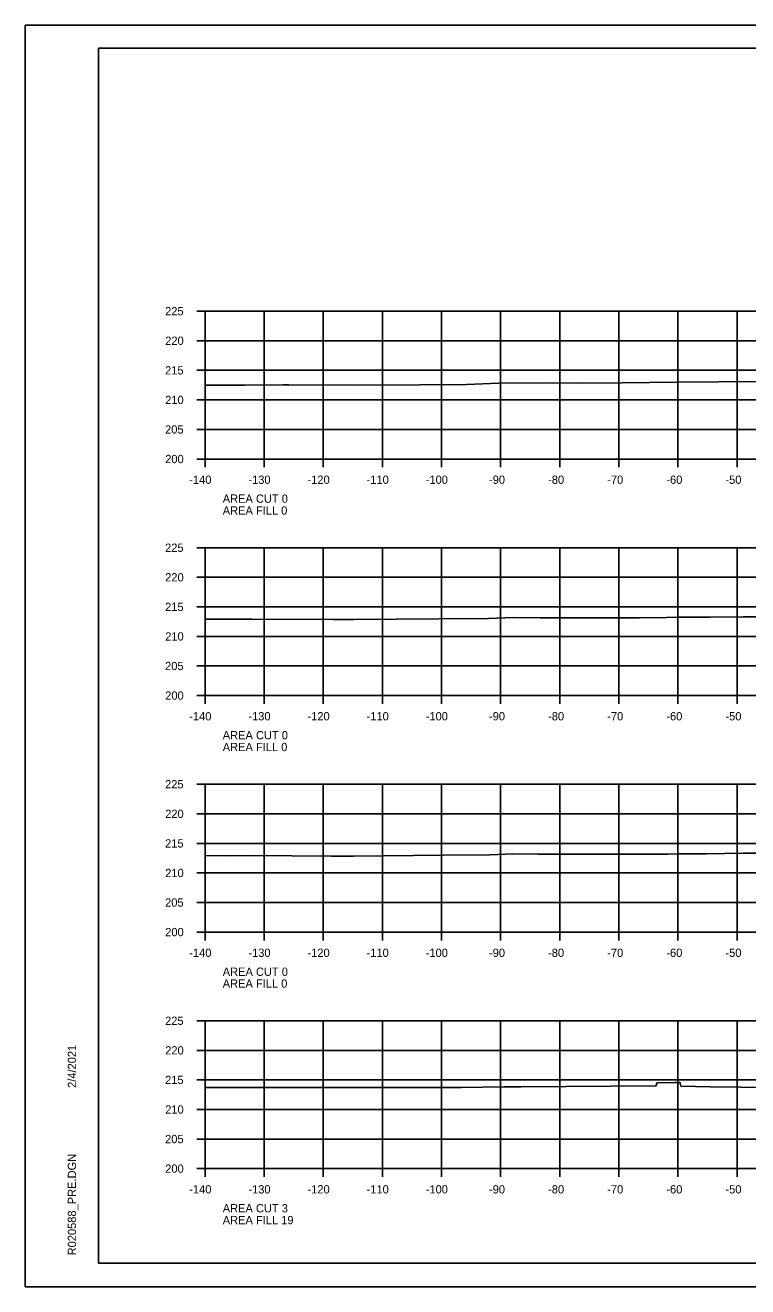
# Model space of a CAD drawing. Extents: x 1368968 to 1369915, y 377395 to 380381.
# Drawn here: x 1369581.4 to 1369703.6, y 379954.8 to 380168.1 of the extents above; entities that cross this region are included whole.
import ezdxf

# ---------------------------------------------------------------- set-up
doc = ezdxf.new("R2010")
doc.units = 0
for name, color, linetype in [('S_BREAKLINE_ANNOT', 7, 'Continuous'), ('S_BRIDGE', 7, 'Continuous'), ('S_BRIDGE_ANNOT', 7, 'Continuous'), ('S_CTL_TABLE', 7, 'Continuous'), ('S_DITCHLINE_ANNOT', 7, 'Continuous'), ('S_DROP_INLET', 7, 'Continuous')]:
    doc.layers.add(name, color=color, linetype=linetype)

msp = doc.modelspace()

# ---------------------------------------------------------------- linework, layer by layer
at = {"layer": 'S_BREAKLINE_ANNOT'}
for p, q in [((1369610.38, 380119.73), (1369611.78, 380119.73)), ((1369611.78, 380094.73), (1369611.78, 380119.73)), ((1369610.38, 380114.73), (1369611.78, 380114.73)), ((1369610.38, 380109.73), (1369611.78, 380109.73)), ((1369610.38, 380104.73), (1369611.78, 380104.73)), ((1369610.38, 380099.73), (1369611.78, 380099.73)), ((1369610.38, 380094.73), (1369611.78, 380094.73)), ((1369611.78, 380094.73), (1369891.78, 380094.73)), ((1369611.78, 380093.33), (1369611.78, 380094.73)), ((1369621.78, 380093.33), (1369621.78, 380094.73)), ((1369631.78, 380093.33), (1369631.78, 380094.73)), ((1369641.78, 380093.33), (1369641.78, 380094.73)), ((1369651.78, 380093.33), (1369651.78, 380094.73)), ((1369661.78, 380093.33), (1369661.78, 380094.73)), ((1369671.78, 380093.33), (1369671.78, 380094.73)), ((1369681.78, 380093.33), (1369681.78, 380094.73)), ((1369691.78, 380093.33), (1369691.78, 380094.73)), ((1369701.78, 380093.33), (1369701.78, 380094.73)), ((1369610.38, 380079.73), (1369611.78, 380079.73)), ((1369611.78, 380054.73), (1369611.78, 380079.73)), ((1369610.38, 380074.73), (1369611.78, 380074.73)), ((1369610.38, 380069.73), (1369611.78, 380069.73)), ((1369610.38, 380064.73), (1369611.78, 380064.73)), ((1369610.38, 380059.73), (1369611.78, 380059.73)), ((1369610.38, 380054.73), (1369611.78, 380054.73)), ((1369611.78, 380054.73), (1369891.78, 380054.73)), ((1369611.78, 380053.33), (1369611.78, 380054.73)), ((1369621.78, 380053.33), (1369621.78, 380054.73)), ((1369631.78, 380053.33), (1369631.78, 380054.73)), ((1369641.78, 380053.33), (1369641.78, 380054.73)), ((1369651.78, 380053.33), (1369651.78, 380054.73)), ((1369661.78, 380053.33), (1369661.78, 380054.73)), ((1369671.78, 380053.33), (1369671.78, 380054.73)), ((1369681.78, 380053.33), (1369681.78, 380054.73)), ((1369691.78, 380053.33), (1369691.78, 380054.73)), ((1369701.78, 380053.33), (1369701.78, 380054.73)), ((1369610.38, 380039.73), (1369611.78, 380039.73)), ((1369611.78, 380014.73), (1369611.78, 380039.73)), ((1369610.38, 380034.73), (1369611.78, 380034.73)), ((1369610.38, 380029.73), (1369611.78, 380029.73)), ((1369610.38, 380024.73), (1369611.78, 380024.73)), ((1369610.38, 380019.73), (1369611.78, 380019.73)), ((1369610.38, 380014.73), (1369611.78, 380014.73)), ((1369611.78, 380014.73), (1369891.78, 380014.73)), ((1369611.78, 380013.33), (1369611.78, 380014.73)), ((1369621.78, 380013.33), (1369621.78, 380014.73)), ((1369631.78, 380013.33), (1369631.78, 380014.73)), ((1369641.78, 380013.33), (1369641.78, 380014.73)), ((1369651.78, 380013.33), (1369651.78, 380014.73)), ((1369661.78, 380013.33), (1369661.78, 380014.73)), ((1369671.78, 380013.33), (1369671.78, 380014.73)), ((1369681.78, 380013.33), (1369681.78, 380014.73)), ((1369691.78, 380013.33), (1369691.78, 380014.73)), ((1369701.78, 380013.33), (1369701.78, 380014.73)), ((1369610.38, 379999.73), (1369611.78, 379999.73)), ((1369611.78, 379974.73), (1369611.78, 379999.73)), ((1369610.38, 379994.73), (1369611.78, 379994.73)), ((1369610.38, 379989.73), (1369611.78, 379989.73)), ((1369610.38, 379984.73), (1369611.78, 379984.73)), ((1369610.38, 379979.73), (1369611.78, 379979.73)), ((1369610.38, 379974.73), (1369611.78, 379974.73)), ((1369611.78, 379974.73), (1369891.78, 379974.73)), ((1369611.78, 379973.33), (1369611.78, 379974.73)), ((1369621.78, 379973.33), (1369621.78, 379974.73)), ((1369631.78, 379973.33), (1369631.78, 379974.73)), ((1369641.78, 379973.33), (1369641.78, 379974.73)), ((1369651.78, 379973.33), (1369651.78, 379974.73)), ((1369661.78, 379973.33), (1369661.78, 379974.73)), ((1369671.78, 379973.33), (1369671.78, 379974.73)), ((1369681.78, 379973.33), (1369681.78, 379974.73)), ((1369691.78, 379973.33), (1369691.78, 379974.73)), ((1369701.78, 379973.33), (1369701.78, 379974.73))]:
    msp.add_line(p, q, dxfattribs=at)
at = {"layer": 'S_BRIDGE_ANNOT'}
for p, q in [((1369593.78, 380164.19), (1369909.96, 380164.19)), ((1369593.78, 379958.73), (1369593.78, 380164.19)), ((1369593.78, 379958.73), (1369593.78, 379958.73)), ((1369909.96, 379958.73), (1369593.78, 379958.73))]:
    msp.add_line(p, q, dxfattribs=at)
at = {"layer": 'S_CTL_TABLE'}
for points in [[(1369611.78, 380107.2), (1369616.62, 380107.2), (1369618.51, 380107.24), (1369625.01, 380107.29), (1369625.95, 380107.27), (1369637.25, 380107.22), (1369648.13, 380107.26), (1369656.06, 380107.33), (1369661.44, 380107.56), (1369669.39, 380107.63), (1369675.16, 380107.58), (1369682.37, 380107.64), (1369691.58, 380107.72), (1369698.6, 380107.78), (1369708.25, 380107.86)], [(1369611.78, 380067.64), (1369615.97, 380067.64), (1369619.72, 380067.64), (1369633.39, 380067.57), (1369636.99, 380067.57), (1369651.31, 380067.72), (1369659.75, 380067.75), (1369663.89, 380067.93), (1369668.5, 380067.9), (1369685.24, 380067.87), (1369689.85, 380067.91), (1369691.96, 380067.97), (1369697.17, 380067.99), (1369702.79, 380068.07), (1369715.64, 380068.07)], [(1369611.78, 380027.66), (1369615.79, 380027.65), (1369619.74, 380027.66), (1369633.16, 380027.58), (1369636.97, 380027.58), (1369652.09, 380027.74), (1369659.99, 380027.77), (1369663.87, 380027.94), (1369668.18, 380027.91), (1369685.92, 380027.89), (1369690.02, 380027.92), (1369691.9, 380027.97), (1369696.53, 380027.99), (1369702.78, 380028.07), (1369715.14, 380028.08)], [(1369611.78, 379988.44), (1369620.83, 379988.44), (1369621.43, 379988.43), (1369635.78, 379988.44), (1369637.31, 379988.45), (1369651.26, 379988.45), (1369655.13, 379988.47), (1369662.37, 379988.55), (1369665.28, 379988.54), (1369688.05, 379988.71), (1369688.09, 379988.84), (1369688.24, 379989.25), (1369691.26, 379989.28), (1369692.12, 379989.27), (1369692.16, 379989.15), (1369692.28, 379988.7), (1369697.24, 379988.58), (1369702.4, 379988.48), (1369707.46, 379988.47)]]:
    msp.add_lwpolyline(points, dxfattribs=at)
at = {"layer": 'S_DITCHLINE_ANNOT'}
for p, q in [((1369611.78, 380119.73), (1369891.78, 380119.73)), ((1369611.78, 380094.73), (1369611.78, 380119.73)), ((1369621.78, 380094.73), (1369621.78, 380119.73)), ((1369631.78, 380094.73), (1369631.78, 380119.73)), ((1369641.78, 380094.73), (1369641.78, 380119.73)), ((1369651.78, 380094.73), (1369651.78, 380119.73)), ((1369661.78, 380094.73), (1369661.78, 380119.73)), ((1369671.78, 380094.73), (1369671.78, 380119.73)), ((1369681.78, 380094.73), (1369681.78, 380119.73)), ((1369691.78, 380094.73), (1369691.78, 380119.73)), ((1369701.78, 380094.73), (1369701.78, 380119.73)), ((1369611.78, 380114.73), (1369891.78, 380114.73)), ((1369611.78, 380109.73), (1369891.78, 380109.73)), ((1369611.78, 380104.73), (1369891.78, 380104.73)), ((1369611.78, 380099.73), (1369891.78, 380099.73)), ((1369611.78, 380094.73), (1369891.78, 380094.73)), ((1369611.78, 380079.73), (1369891.78, 380079.73)), ((1369611.78, 380054.73), (1369611.78, 380079.73)), ((1369621.78, 380054.73), (1369621.78, 380079.73)), ((1369631.78, 380054.73), (1369631.78, 380079.73)), ((1369641.78, 380054.73), (1369641.78, 380079.73)), ((1369651.78, 380054.73), (1369651.78, 380079.73)), ((1369661.78, 380054.73), (1369661.78, 380079.73)), ((1369671.78, 380054.73), (1369671.78, 380079.73)), ((1369681.78, 380054.73), (1369681.78, 380079.73)), ((1369691.78, 380054.73), (1369691.78, 380079.73)), ((1369701.78, 380054.73), (1369701.78, 380079.73)), ((1369611.78, 380074.73), (1369891.78, 380074.73)), ((1369611.78, 380069.73), (1369891.78, 380069.73)), ((1369611.78, 380064.73), (1369891.78, 380064.73)), ((1369611.78, 380059.73), (1369891.78, 380059.73)), ((1369611.78, 380054.73), (1369891.78, 380054.73)), ((1369611.78, 380039.73), (1369891.78, 380039.73)), ((1369611.78, 380014.73), (1369611.78, 380039.73)), ((1369621.78, 380014.73), (1369621.78, 380039.73)), ((1369631.78, 380014.73), (1369631.78, 380039.73)), ((1369641.78, 380014.73), (1369641.78, 380039.73)), ((1369651.78, 380014.73), (1369651.78, 380039.73)), ((1369661.78, 380014.73), (1369661.78, 380039.73)), ((1369671.78, 380014.73), (1369671.78, 380039.73)), ((1369681.78, 380014.73), (1369681.78, 380039.73)), ((1369691.78, 380014.73), (1369691.78, 380039.73)), ((1369701.78, 380014.73), (1369701.78, 380039.73)), ((1369611.78, 380034.73), (1369891.78, 380034.73)), ((1369611.78, 380029.73), (1369891.78, 380029.73)), ((1369611.78, 380024.73), (1369891.78, 380024.73)), ((1369611.78, 380019.73), (1369891.78, 380019.73)), ((1369611.78, 380014.73), (1369891.78, 380014.73)), ((1369611.78, 379999.73), (1369891.78, 379999.73)), ((1369611.78, 379974.73), (1369611.78, 379999.73)), ((1369621.78, 379974.73), (1369621.78, 379999.73)), ((1369631.78, 379974.73), (1369631.78, 379999.73)), ((1369641.78, 379974.73), (1369641.78, 379999.73)), ((1369651.78, 379974.73), (1369651.78, 379999.73)), ((1369661.78, 379974.73), (1369661.78, 379999.73)), ((1369671.78, 379974.73), (1369671.78, 379999.73)), ((1369681.78, 379974.73), (1369681.78, 379999.73)), ((1369691.78, 379974.73), (1369691.78, 379999.73)), ((1369701.78, 379974.73), (1369701.78, 379999.73)), ((1369611.78, 379994.73), (1369891.78, 379994.73)), ((1369611.78, 379989.73), (1369891.78, 379989.73)), ((1369611.78, 379984.73), (1369891.78, 379984.73)), ((1369611.78, 379979.73), (1369891.78, 379979.73)), ((1369611.78, 379974.73), (1369891.78, 379974.73))]:
    msp.add_line(p, q, dxfattribs=at)
at = {"layer": 'S_DROP_INLET'}
for p, q in [((1369581.38, 380168.09), (1369914.71, 380168.09)), ((1369581.38, 379954.75), (1369914.71, 379954.75))]:
    msp.add_line(p, q, dxfattribs=at)
for points in [[(1369581.37, 380168.09), (1369914.71, 380168.09), (1369914.71, 379954.75), (1369581.37, 379954.75)], [(1369827.7, 380164.19), (1369827.7, 380154.31), (1369863.43, 380154.31), (1369863.43, 380151.39), (1369886.63, 380151.39), (1369886.63, 380127.06), (1369909.96, 380127.06), (1369909.96, 379958.73), (1369593.78, 379958.73), (1369593.78, 380164.19)]]:
    msp.add_lwpolyline(points, close=True, dxfattribs=at)

# ---------------------------------------------------------------- texts
at = {"layer": 'S_BRIDGE'}
for s, p in [('225', (1369605.03, 380119.03)), ('220', (1369605.05, 380114.03)), ('215', (1369605.03, 380109.03)), ('210', (1369605.05, 380104.03)), ('205', (1369605.03, 380099.03)), ('200', (1369605.05, 380094.03)), ('-140', (1369609.12, 380090.53)), ('-130', (1369619.12, 380090.53)), ('-120', (1369629.12, 380090.53)), ('-110', (1369639.12, 380090.53)), ('-100', (1369649.12, 380090.53)), ('-90', (1369659.82, 380090.53)), ('-80', (1369669.82, 380090.53)), ('-70', (1369679.82, 380090.53)), ('-60', (1369689.82, 380090.53)), ('-50', (1369699.82, 380090.53)), ('AREA CUT 0', (1369614.78, 380087.33)), ('AREA FILL 0', (1369614.78, 380085.33)), ('225', (1369605.03, 380079.03)), ('220', (1369605.05, 380074.03)), ('215', (1369605.03, 380069.03)), ('210', (1369605.05, 380064.03)), ('205', (1369605.03, 380059.03)), ('200', (1369605.05, 380054.03)), ('-140', (1369609.12, 380050.53)), ('-130', (1369619.12, 380050.53)), ('-120', (1369629.12, 380050.53)), ('-110', (1369639.12, 380050.53)), ('-100', (1369649.12, 380050.53)), ('-90', (1369659.82, 380050.53)), ('-80', (1369669.82, 380050.53)), ('-70', (1369679.82, 380050.53)), ('-60', (1369689.82, 380050.53)), ('-50', (1369699.82, 380050.53)), ('AREA CUT 0', (1369614.78, 380047.33)), ('AREA FILL 0', (1369614.78, 380045.33)), ('225', (1369605.03, 380039.03)), ('220', (1369605.05, 380034.03)), ('215', (1369605.03, 380029.03)), ('210', (1369605.05, 380024.03)), ('205', (1369605.03, 380019.03)), ('200', (1369605.05, 380014.03)), ('-140', (1369609.12, 380010.53)), ('-130', (1369619.12, 380010.53)), ('-120', (1369629.12, 380010.53)), ('-110', (1369639.12, 380010.53)), ('-100', (1369649.12, 380010.53)), ('-90', (1369659.82, 380010.53)), ('-80', (1369669.82, 380010.53)), ('-70', (1369679.82, 380010.53)), ('-60', (1369689.82, 380010.53)), ('-50', (1369699.82, 380010.53)), ('AREA CUT 0', (1369614.78, 380007.33)), ('AREA FILL 0', (1369614.78, 380005.33)), ('225', (1369605.03, 379999.03)), ('220', (1369605.05, 379994.03)), ('215', (1369605.03, 379989.03)), ('210', (1369605.05, 379984.03)), ('205', (1369605.03, 379979.03)), ('200', (1369605.05, 379974.03)), ('-140', (1369609.12, 379970.53)), ('-130', (1369619.12, 379970.53)), ('-120', (1369629.12, 379970.53)), ('-110', (1369639.12, 379970.53)), ('-100', (1369649.12, 379970.53)), ('-90', (1369659.82, 379970.53)), ('-80', (1369669.82, 379970.53)), ('-70', (1369679.82, 379970.53)), ('-60', (1369689.82, 379970.53)), ('-50', (1369699.82, 379970.53)), ('AREA CUT 3', (1369614.78, 379967.33)), ('AREA FILL 19', (1369614.78, 379965.33))]:
    msp.add_text(s, height=1.4, dxfattribs=at).set_placement(p)
at = {"layer": 'S_BRIDGE_ANNOT'}
for s, p in [('2/4/2021', (1369589.97, 379988.38)), ('R020588_PRE.DGN', (1369589.97, 379960.06))]:
    msp.add_text(s, height=1.4, rotation=90, dxfattribs=at).set_placement(p)

doc.saveas('drawing.dxf')
